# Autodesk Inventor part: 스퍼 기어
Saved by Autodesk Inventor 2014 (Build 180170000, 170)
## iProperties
Created: 2026-08
Part Number: 스퍼 기어
Material: 일반
Document SubType Name: Modeling
Designer: dg
Density: 1 g/cm^3
Appearance: 기본값
Author: dg
Author: jhkim
Creation Date: 2026-07-31
Sending System: Autodesk Inventor 2027
Preprocessor: ST-DEVELOPER v20.1
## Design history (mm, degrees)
node "스퍼 기어1"
node "솔리드1"
node "기준1"
